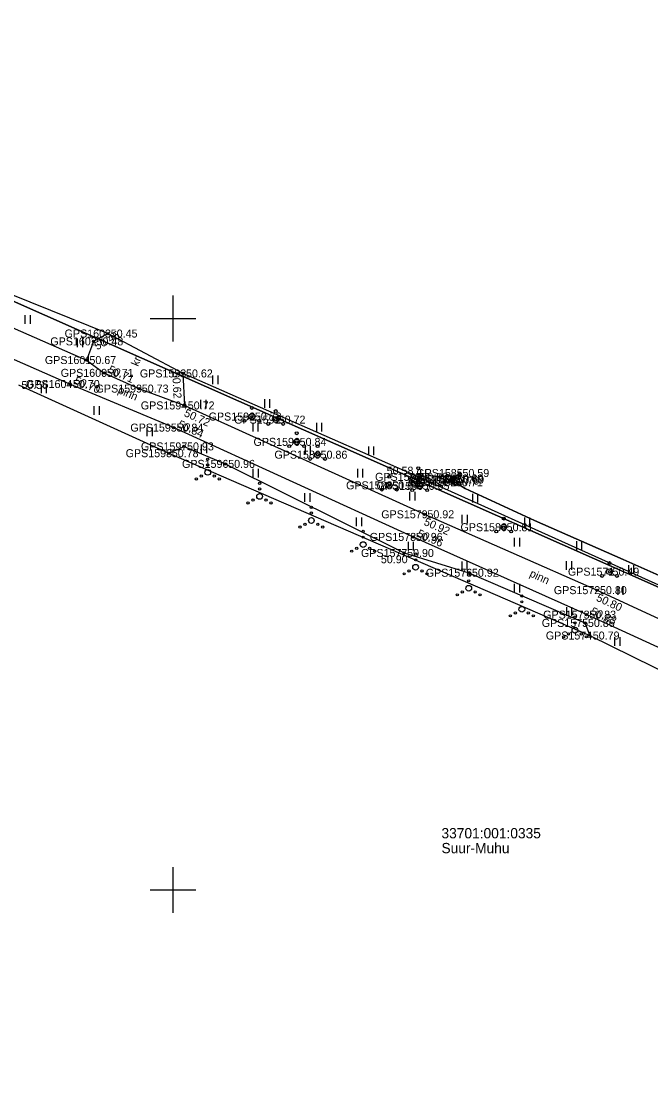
# Model space of a CAD drawing. Extents: x 551623 to 559850, y 6561220 to 6567135.
# Drawn here: x 556436.7 to 556491.8, y 6565132 to 6565226 of the extents above; entities that cross this region are included whole.
import ezdxf

# ---------------------------------------------------------------- set-up
doc = ezdxf.new("R2010")
doc.units = 0
for name, color, linetype in [('ELRAJATISMP', 7, 'Continuous'), ('HALJASTUS', 7, 'Continuous'), ('KORGUS-EH2000', 7, 'Continuous'), ('MOOTKORG-EH2000', 7, 'Continuous'), ('MOOTMPUNKT', 7, 'Continuous'), ('MOOTNR', 7, 'Continuous'), ('MOOTPIIR', 7, 'Continuous'), ('MPKAABEL', 7, 'Continuous'), ('PIIR', 7, 'Continuous'), ('PUU', 7, 'Continuous'), ('TEE', 7, 'Continuous'), ('VORK', 7, 'Continuous')]:
    doc.layers.add(name, color=color, linetype=linetype)

msp = doc.modelspace()

# ---------------------------------------------------------------- linework, layer by layer
at = {"layer": 'ELRAJATISMP'}
for p, q in [((556474.425, 6565186.191), (556474.185, 6565185.645)), ((556474.674, 6565186.081), (556474.433, 6565185.535))]:
    msp.add_line(p, q, dxfattribs=at)
msp.add_lwpolyline([(556474.003, 6565186.377), (556475.096, 6565185.895), (556474.855, 6565185.349), (556473.762, 6565185.831)], close=True, dxfattribs=at)
at = {"layer": 'HALJASTUS'}
for p, q in [((556437.058, 6565200.288), (556437.058, 6565199.527)), ((556437.513, 6565200.288), (556437.513, 6565199.527)), ((556441.627, 6565198.258), (556441.627, 6565197.497)), ((556442.082, 6565198.258), (556442.082, 6565197.497)), ((556438.461, 6565194.219), (556438.461, 6565193.458)), ((556438.916, 6565194.219), (556438.916, 6565193.458)), ((556453.468, 6565195.01), (556453.468, 6565194.249)), ((556453.923, 6565195.01), (556453.923, 6565194.249)), ((556443.095, 6565192.341), (556443.095, 6565191.58)), ((556443.55, 6565192.341), (556443.55, 6565191.58)), ((556452.418, 6565192.893), (556452.418, 6565192.132)), ((556452.873, 6565192.893), (556452.873, 6565192.132)), ((556458.018, 6565192.938), (556458.018, 6565192.177)), ((556458.473, 6565192.938), (556458.473, 6565192.177)), ((556447.729, 6565190.463), (556447.729, 6565189.702)), ((556448.184, 6565190.463), (556448.184, 6565189.702)), ((556456.995, 6565190.881), (556456.995, 6565190.12)), ((556457.45, 6565190.881), (556457.45, 6565190.12)), ((556462.568, 6565190.866), (556462.568, 6565190.104)), ((556463.023, 6565190.866), (556463.023, 6565190.104)), ((556452.492, 6565188.988), (556452.492, 6565188.227)), ((556452.947, 6565188.988), (556452.947, 6565188.227)), ((556461.572, 6565188.868), (556461.572, 6565188.107)), ((556462.027, 6565188.868), (556462.027, 6565188.107)), ((556467.119, 6565188.794), (556467.119, 6565188.032)), ((556467.574, 6565188.794), (556467.574, 6565188.032)), ((556457.014, 6565186.854), (556457.014, 6565186.093)), ((556457.469, 6565186.854), (556457.469, 6565186.093)), ((556466.149, 6565186.855), (556466.149, 6565186.094)), ((556466.604, 6565186.855), (556466.604, 6565186.094)), ((556471.669, 6565186.721), (556471.669, 6565185.96)), ((556472.124, 6565186.721), (556472.124, 6565185.96)), ((556461.535, 6565184.72), (556461.535, 6565183.959)), ((556461.99, 6565184.72), (556461.99, 6565183.959)), ((556470.726, 6565184.842), (556470.726, 6565184.081)), ((556471.181, 6565184.842), (556471.181, 6565184.081)), ((556476.22, 6565184.649), (556476.22, 6565183.888)), ((556476.675, 6565184.649), (556476.675, 6565183.888)), ((556475.303, 6565182.83), (556475.303, 6565182.069)), ((556475.758, 6565182.83), (556475.758, 6565182.069)), ((556466.057, 6565182.585), (556466.057, 6565181.824)), ((556466.512, 6565182.585), (556466.512, 6565181.824)), ((556480.77, 6565182.577), (556480.77, 6565181.816)), ((556481.225, 6565182.577), (556481.225, 6565181.816)), ((556470.582, 6565180.461), (556470.582, 6565179.7)), ((556471.037, 6565180.461), (556471.037, 6565179.7)), ((556479.88, 6565180.817), (556479.88, 6565180.056)), ((556480.335, 6565180.817), (556480.335, 6565180.056)), ((556485.321, 6565180.505), (556485.321, 6565179.744)), ((556485.776, 6565180.505), (556485.776, 6565179.744)), ((556475.281, 6565178.751), (556475.281, 6565177.99)), ((556475.736, 6565178.751), (556475.736, 6565177.99)), ((556484.436, 6565178.759), (556484.436, 6565177.998)), ((556484.892, 6565178.759), (556484.892, 6565177.998)), ((556489.871, 6565178.433), (556489.871, 6565177.672)), ((556490.326, 6565178.433), (556490.326, 6565177.672)), ((556479.874, 6565176.78), (556479.874, 6565176.019)), ((556480.329, 6565176.78), (556480.329, 6565176.019)), ((556488.936, 6565176.579), (556488.936, 6565175.818)), ((556489.391, 6565176.579), (556489.391, 6565175.818)), ((556484.445, 6565174.752), (556484.445, 6565173.991)), ((556484.9, 6565174.752), (556484.9, 6565173.991)), ((556488.663, 6565172.134), (556488.663, 6565171.373)), ((556489.118, 6565172.134), (556489.118, 6565171.373))]:
    msp.add_line(p, q, dxfattribs=at)
msp.add_lwpolyline([(556449.647, 6565188.215), (556450.982, 6565188.808), (556454.582, 6565187.281), (556470.244, 6565179.486), (556475.92, 6565177.757), (556486.071, 6565173.366), (556486.494, 6565172.264)], dxfattribs=at)
for centre, radius in [((556453.056, 6565187.693), 0.1), ((556453.056, 6565186.543), 0.25), ((556453.056, 6565187.193), 0.1), ((556452.056, 6565185.968), 0.1), ((556452.491, 6565186.218), 0.1), ((556453.621, 6565186.218), 0.1), ((556454.056, 6565185.968), 0.1), ((556457.589, 6565185.585), 0.1), ((556457.589, 6565185.085), 0.1), ((556456.589, 6565183.86), 0.1), ((556457.024, 6565184.11), 0.1), ((556457.589, 6565184.435), 0.25), ((556458.154, 6565184.11), 0.1), ((556458.589, 6565183.86), 0.1), ((556462.123, 6565183.476), 0.1), ((556462.123, 6565182.976), 0.1), ((556461.558, 6565182.001), 0.1), ((556462.123, 6565182.326), 0.25), ((556462.688, 6565182.001), 0.1), ((556461.123, 6565181.751), 0.1), ((556463.123, 6565181.751), 0.1), ((556466.657, 6565181.368), 0.1), ((556466.657, 6565180.868), 0.1), ((556466.657, 6565180.218), 0.25), ((556465.657, 6565179.643), 0.1), ((556466.092, 6565179.893), 0.1), ((556467.222, 6565179.893), 0.1), ((556467.657, 6565179.643), 0.1), ((556471.244, 6565179.385), 0.1), ((556471.244, 6565178.235), 0.25), ((556471.244, 6565178.885), 0.1), ((556470.244, 6565177.66), 0.1), ((556470.679, 6565177.91), 0.1), ((556471.809, 6565177.91), 0.1), ((556472.244, 6565177.66), 0.1), ((556475.895, 6565177.548), 0.1), ((556475.895, 6565176.398), 0.25), ((556475.895, 6565177.048), 0.1), ((556474.895, 6565175.823), 0.1), ((556475.33, 6565176.073), 0.1), ((556476.46, 6565176.073), 0.1), ((556476.895, 6565175.823), 0.1), ((556480.545, 6565175.71), 0.1), ((556480.545, 6565175.21), 0.1), ((556480.545, 6565174.56), 0.25), ((556479.545, 6565173.985), 0.1), ((556479.98, 6565174.235), 0.1), ((556481.11, 6565174.235), 0.1), ((556481.545, 6565173.985), 0.1), ((556485.195, 6565173.873), 0.1), ((556485.195, 6565173.373), 0.1), ((556484.63, 6565172.398), 0.1), ((556485.195, 6565172.723), 0.25), ((556485.76, 6565172.398), 0.1), ((556484.195, 6565172.148), 0.1), ((556486.195, 6565172.148), 0.1)]:
    msp.add_circle(centre, radius, dxfattribs=at)
at = {"layer": 'KORGUS-EH2000'}
for centre in [(556444.303, 6565198.685), (556443.964, 6565195.244), (556450.892, 6565195.194), (556440.995, 6565194.267), (556451.044, 6565192.394), (556450.062, 6565190.454), (556459.004, 6565191.153), (556449.647, 6565188.215), (556471.481, 6565186.145), (556472.021, 6565182.87), (556471.011, 6565180.892), (556470.244, 6565179.486), (556488.218, 6565177.852), (556487.128, 6565176.233), (556486.192, 6565174.091), (556486.494, 6565172.264)]:
    msp.add_circle(centre, 0.1, dxfattribs=at)
at = {"layer": 'MOOTMPUNKT'}
for centre in [(556443.054, 6565197.997), (556444.303, 6565198.685), (556442.438, 6565196.365), (556443.964, 6565195.244), (556450.892, 6565195.194), (556440.995, 6565194.267), (556447.02, 6565193.867), (556451.044, 6565192.394), (556456.912, 6565191.423), (556450.062, 6565190.454), (556459.004, 6565191.153), (556450.982, 6565188.808), (556460.838, 6565189.207), (556449.647, 6565188.215), (556462.671, 6565188.085), (556454.582, 6565187.281), (556475.088, 6565186.483), (556471.481, 6565186.145), (556474.217, 6565185.809), (556474.525, 6565185.673), (556474.569, 6565186.004), (556474.641, 6565185.917), (556468.942, 6565185.402), (556471.608, 6565185.357), (556472.021, 6565182.87), (556471.011, 6565180.892), (556478.956, 6565181.739), (556470.244, 6565179.486), (556475.92, 6565177.757), (556488.218, 6565177.852), (556487.128, 6565176.233), (556486.071, 6565173.366), (556486.192, 6565174.091), (556486.494, 6565172.264)]:
    msp.add_circle(centre, 0.1, dxfattribs=at)
at = {"layer": 'MOOTPIIR'}
for points in [[(556752.299, 6565224.302), (556722.286, 6565214.456), (556699.828, 6565206.048), (556676.45, 6565195.172), (556655.692, 6565185.071), (556630.484, 6565174.696), (556604.291, 6565163.073), (556579.273, 6565154.176), (556570.04, 6565150.556), (556566.682, 6565150.593), (556559.96, 6565151.833), (556559.005, 6565148.531), (556554.988, 6565148.026), (556532.572, 6565157.699), (556503.633, 6565171.674), (556471.481, 6565186.145), (556450.892, 6565195.194), (556444.303, 6565198.685), (556419.033, 6565208.861)], [(556436.48, 6565194.185), (556449.647, 6565188.215), (556486.494, 6565172.264), (556501.317, 6565164.974), (556534.661, 6565148.753), (556550.886, 6565142.039), (556560.868, 6565140.849), (556563.777, 6565138.667), (556564.947, 6565140.416), (556574.124, 6565143.095), (556582.549, 6565147.264), (556608.526, 6565156.509), (556634.616, 6565167.336), (556657.454, 6565177.431), (556678.781, 6565185.856), (556704.754, 6565195.238), (556727.607, 6565205.59), (556758.128, 6565217.782)]]:
    msp.add_lwpolyline(points, dxfattribs=at)
at = {"layer": 'MPKAABEL'}
msp.add_line((556475.088, 6565186.483), (556474.429, 6565185.863), dxfattribs=at)
for points in [[(556542.186, 6565155.587), (556534.74, 6565158.962), (556527.019, 6565162.424), (556518.017, 6565166.315), (556508.757, 6565170.404), (556506.182, 6565171.529), (556499.627, 6565174.391), (556495.193, 6565176.354), (556489.402, 6565178.918), (556481.664, 6565182.326), (556475.594, 6565185.123), (556474.429, 6565185.863)], [(556474.429, 6565185.863), (556475.594, 6565185.123), (556481.664, 6565182.326), (556489.402, 6565178.918), (556495.193, 6565176.354)]]:
    msp.add_lwpolyline(points, dxfattribs=at)
at = {"layer": 'PIIR'}
for points in [[(556217.39, 6565298.59), (556213.87, 6565303.19), (556229.81, 6565311.25), (556335.44, 6565331.24), (556350.73, 6565342.07), (556507.54, 6565334), (556519.21, 6565368.05), (556548.5, 6565368.1), (556612.15, 6565380.04), (556615.14, 6565380.2), (556613.56, 6565366.23), (556611.32, 6565356.67), (556591.74, 6565273.2), (556570.09, 6565180.67), (556561.87, 6565145.74), (556557.67, 6565147.61), (556393.49, 6565220.36)], [(556393.49, 6565220.36), (556557.67, 6565147.61), (556561.87, 6565145.74), (556518.27, 6565016.8), (556485.25, 6564921.4), (556406.78, 6564699.5), (556400.89, 6564700.63), (556129.6, 6564752.43), (556228.34, 6565008.72), (556274.8, 6564990.28)]]:
    msp.add_lwpolyline(points, close=True, dxfattribs=at)
at = {"layer": 'PUU'}
for centre, radius in [((556456.912, 6565192.173), 0.125), ((556456.912, 6565191.423), 0.25), ((556459.004, 6565191.153), 0.25), ((556459.004, 6565191.903), 0.125), ((556456.262, 6565191.048), 0.125), ((556457.562, 6565191.048), 0.125), ((556458.354, 6565190.778), 0.125), ((556459.654, 6565190.778), 0.125), ((556460.838, 6565189.207), 0.25), ((556460.838, 6565189.957), 0.125), ((556460.188, 6565188.832), 0.125), ((556461.488, 6565188.832), 0.125), ((556462.671, 6565188.835), 0.125), ((556462.021, 6565187.71), 0.125), ((556462.671, 6565188.085), 0.25), ((556463.321, 6565187.71), 0.125), ((556471.481, 6565186.895), 0.125), ((556468.942, 6565185.402), 0.25), ((556468.942, 6565186.152), 0.125), ((556470.831, 6565185.77), 0.125), ((556471.481, 6565186.145), 0.25), ((556471.608, 6565186.107), 0.125), ((556472.131, 6565185.77), 0.125), ((556468.292, 6565185.027), 0.125), ((556469.592, 6565185.027), 0.125), ((556470.958, 6565184.982), 0.125), ((556471.608, 6565185.357), 0.25), ((556472.258, 6565184.982), 0.125), ((556478.956, 6565181.739), 0.25), ((556478.956, 6565182.489), 0.125), ((556478.306, 6565181.364), 0.125), ((556479.606, 6565181.364), 0.125), ((556488.218, 6565178.602), 0.125), ((556487.568, 6565177.477), 0.125), ((556488.218, 6565177.852), 0.25), ((556488.868, 6565177.477), 0.125)]:
    msp.add_circle(centre, radius, dxfattribs=at)
at = {"layer": 'TEE'}
for points in [[(556212.519, 6565297.656), (556233.204, 6565288.814), (556257.431, 6565277.885), (556277.379, 6565268.878), (556295.258, 6565260.972), (556307.223, 6565255.623), (556319.32, 6565250.223), (556331.627, 6565244.871), (556340.735, 6565240.974), (556360.587, 6565232.345), (556381.381, 6565222.917), (556405.852, 6565212.41), (556418.096, 6565207.028), (556442.438, 6565196.365)], [(556563.777, 6565138.667), (556560.868, 6565140.849), (556553.174, 6565143.6), (556545.589, 6565147.013), (556535.182, 6565151.57), (556522.842, 6565156.959), (556502.184, 6565166.778), (556486.192, 6565174.091), (556471.011, 6565180.892), (556450.062, 6565190.454), (556440.995, 6565194.267), (556416.948, 6565204.811), (556405, 6565210.263), (556380.262, 6565220.954), (556359.747, 6565229.991), (556339.784, 6565238.7), (556330.661, 6565242.666), (556318.495, 6565248.069), (556305.998, 6565253.52), (556294.082, 6565258.94), (556276.195, 6565266.757), (556256.289, 6565275.582), (556232.166, 6565286.787), (556209.59, 6565295.964)], [(556444.303, 6565198.685), (556443.054, 6565197.997), (556442.438, 6565196.365), (556443.964, 6565195.244), (556447.02, 6565193.867), (556451.044, 6565192.394), (556450.892, 6565195.194)], [(556451.044, 6565192.394), (556472.021, 6565182.87), (556487.128, 6565176.233), (556503.051, 6565168.872), (556523.576, 6565158.838), (556536.005, 6565153.683), (556546.609, 6565149.031), (556553.919, 6565145.585), (556561.595, 6565142.591), (556564.947, 6565140.416)]]:
    msp.add_lwpolyline(points, dxfattribs=at)
at = {"layer": 'VORK'}
for p, q in [((556450, 6565202), (556450, 6565198)), ((556448, 6565200), (556452, 6565200)), ((556450, 6565152), (556450, 6565148)), ((556448, 6565150), (556452, 6565150))]:
    msp.add_line(p, q, dxfattribs=at)

# ---------------------------------------------------------------- texts
at = {"layer": 'KORGUS-EH2000'}
for s, rotation, p in [(' 50.45', 28.81625, (556443.147, 6565197.089)), (' 50.71', 335.75682, (556444.036, 6565195.403)), (' 50.62', 273.11965, (556449.927, 6565195.575)), (' 50.70', 337.19409, (556441.063, 6565194.428)), (' 50.72', 335.57994, (556450.682, 6565191.598)), (' 50.84', 335.46592, (556450.135, 6565190.613)), (' 50.92', 336.2829, (556471.669, 6565182.069)), (' 50.96', 335.86776, (556471.083, 6565181.052)), (' 50.80', 335.18902, (556486.761, 6565175.439)), (' 50.83', 335.42607, (556486.265, 6565174.25))]:
    msp.add_text(s, height=0.7, rotation=rotation, dxfattribs=at).set_placement(p)
for s, p in [(' 50.56', (556436.48, 6565193.835)), (' 50.72', (556459.004, 6565190.803)), (' 50.78', (556449.647, 6565187.865)), (' 50.58', (556468.454, 6565186.332)), (' 50.90', (556467.947, 6565178.588)), (' 50.49', (556488.218, 6565177.502)), (' 50.79', (556486.494, 6565171.914))]:
    msp.add_text(s, height=0.7, dxfattribs=at).set_placement(p)
at = {"layer": 'MOOTKORG-EH2000'}
for s, p in [(' 50.45', (556444.303, 6565198.335)), (' 50.48', (556443.054, 6565197.647)), (' 50.67', (556442.438, 6565196.015)), (' 50.71', (556443.964, 6565194.894)), (' 50.62', (556450.892, 6565194.844)), (' 50.56', (556436.48, 6565193.835)), (' 50.70', (556440.995, 6565193.917)), (' 50.73', (556447.02, 6565193.518)), (' 50.72', (556451.044, 6565192.044)), (' 50.73', (556456.912, 6565191.073)), (' 50.72', (556459.004, 6565190.803)), (' 50.84', (556450.062, 6565190.104)), (' 50.84', (556460.838, 6565188.857)), (' 50.78', (556449.647, 6565187.865)), (' 50.93', (556450.982, 6565188.458)), (' 50.96', (556454.582, 6565186.931)), (' 50.86', (556462.671, 6565187.735)), (' 50.59', (556475.088, 6565186.133)), (' 50.84', (556468.942, 6565185.052)), (' 50.58', (556471.481, 6565185.795)), (' 50.65', (556471.608, 6565185.007)), (' 50.70', (556474.217, 6565185.459)), (' 50.71', (556474.525, 6565185.323)), (' 50.69', (556474.569, 6565185.654)), (' 50.69', (556474.641, 6565185.567)), (' 50.92', (556472.021, 6565182.52)), (' 50.81', (556478.956, 6565181.389)), (' 50.96', (556471.011, 6565180.542)), (' 50.90', (556470.244, 6565179.136)), (' 50.92', (556475.92, 6565177.407)), (' 50.49', (556488.218, 6565177.502)), (' 50.80', (556487.128, 6565175.883)), (' 50.83', (556486.192, 6565173.741)), (' 50.86', (556486.071, 6565173.016)), (' 50.79', (556486.494, 6565171.914))]:
    msp.add_text(s, height=0.7, dxfattribs=at).set_placement(p)
at = {"layer": 'MOOTNR'}
for s, p in [('GPS1603 ', (556440.524, 6565198.335)), ('GPS1602 ', (556439.274, 6565197.647)), ('GPS1601 ', (556438.798, 6565196.015)), ('GPS1600 ', (556440.184, 6565194.894)), ('GPS1593 ', (556447.112, 6565194.844)), ('GPS1604 ', (556437.145, 6565193.917)), ('GPS1599 ', (556443.24, 6565193.518)), ('GPS1594 ', (556447.194, 6565192.044)), ('GPS1592 ', (556453.132, 6565191.073)), ('GPS1591 ', (556455.364, 6565190.803)), ('GPS1595 ', (556446.282, 6565190.104)), ('GPS1590 ', (556457.059, 6565188.857)), ('GPS1598 ', (556445.867, 6565187.865)), ('GPS1597 ', (556447.203, 6565188.458)), ('GPS1596 ', (556450.802, 6565186.931)), ('GPS1589 ', (556458.891, 6565187.735)), ('GPS1585 ', (556471.308, 6565186.133)), ('GPS1588 ', (556465.162, 6565185.052)), ('GPS1587 ', (556467.701, 6565185.795)), ('GPS1586 ', (556467.829, 6565185.007)), ('GPS1581 ', (556470.577, 6565185.459)), ('GPS1584 ', (556470.719, 6565185.654)), ('GPS1582 ', (556470.746, 6565185.323)), ('GPS1583 ', (556470.861, 6565185.567)), ('GPS1579 ', (556468.241, 6565182.52)), ('GPS1580 ', (556475.176, 6565181.389)), ('GPS1578 ', (556467.232, 6565180.542)), ('GPS1577 ', (556466.464, 6565179.136)), ('GPS1576 ', (556472.14, 6565177.407)), ('GPS1571 ', (556484.579, 6565177.502)), ('GPS1572 ', (556483.348, 6565175.883)), ('GPS1573 ', (556482.413, 6565173.741)), ('GPS1575 ', (556482.291, 6565173.016)), ('GPS1574 ', (556482.645, 6565171.914))]:
    msp.add_text(s, height=0.7, dxfattribs=at).set_placement(p)
at = {"layer": 'PIIR'}
for s, p in [('33701:001:0335', (556473.512, 6565154.519)), ('Suur-Muhu', (556473.512, 6565153.219))]:
    msp.add_text(s, height=0.9, dxfattribs=at).set_placement(p)
at = {"layer": 'TEE'}
for s, rotation, p in [('kr', 67.25272, (556446.952, 6565195.762)), ('pinn', 336.54684, (556445.123, 6565193.503)), ('pinn', 335.45838, (556481.161, 6565177.457))]:
    msp.add_text(s, height=0.7, rotation=rotation, dxfattribs=at).set_placement(p)

doc.saveas('drawing.dxf')
